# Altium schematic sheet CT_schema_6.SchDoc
size 257 x 245 mm
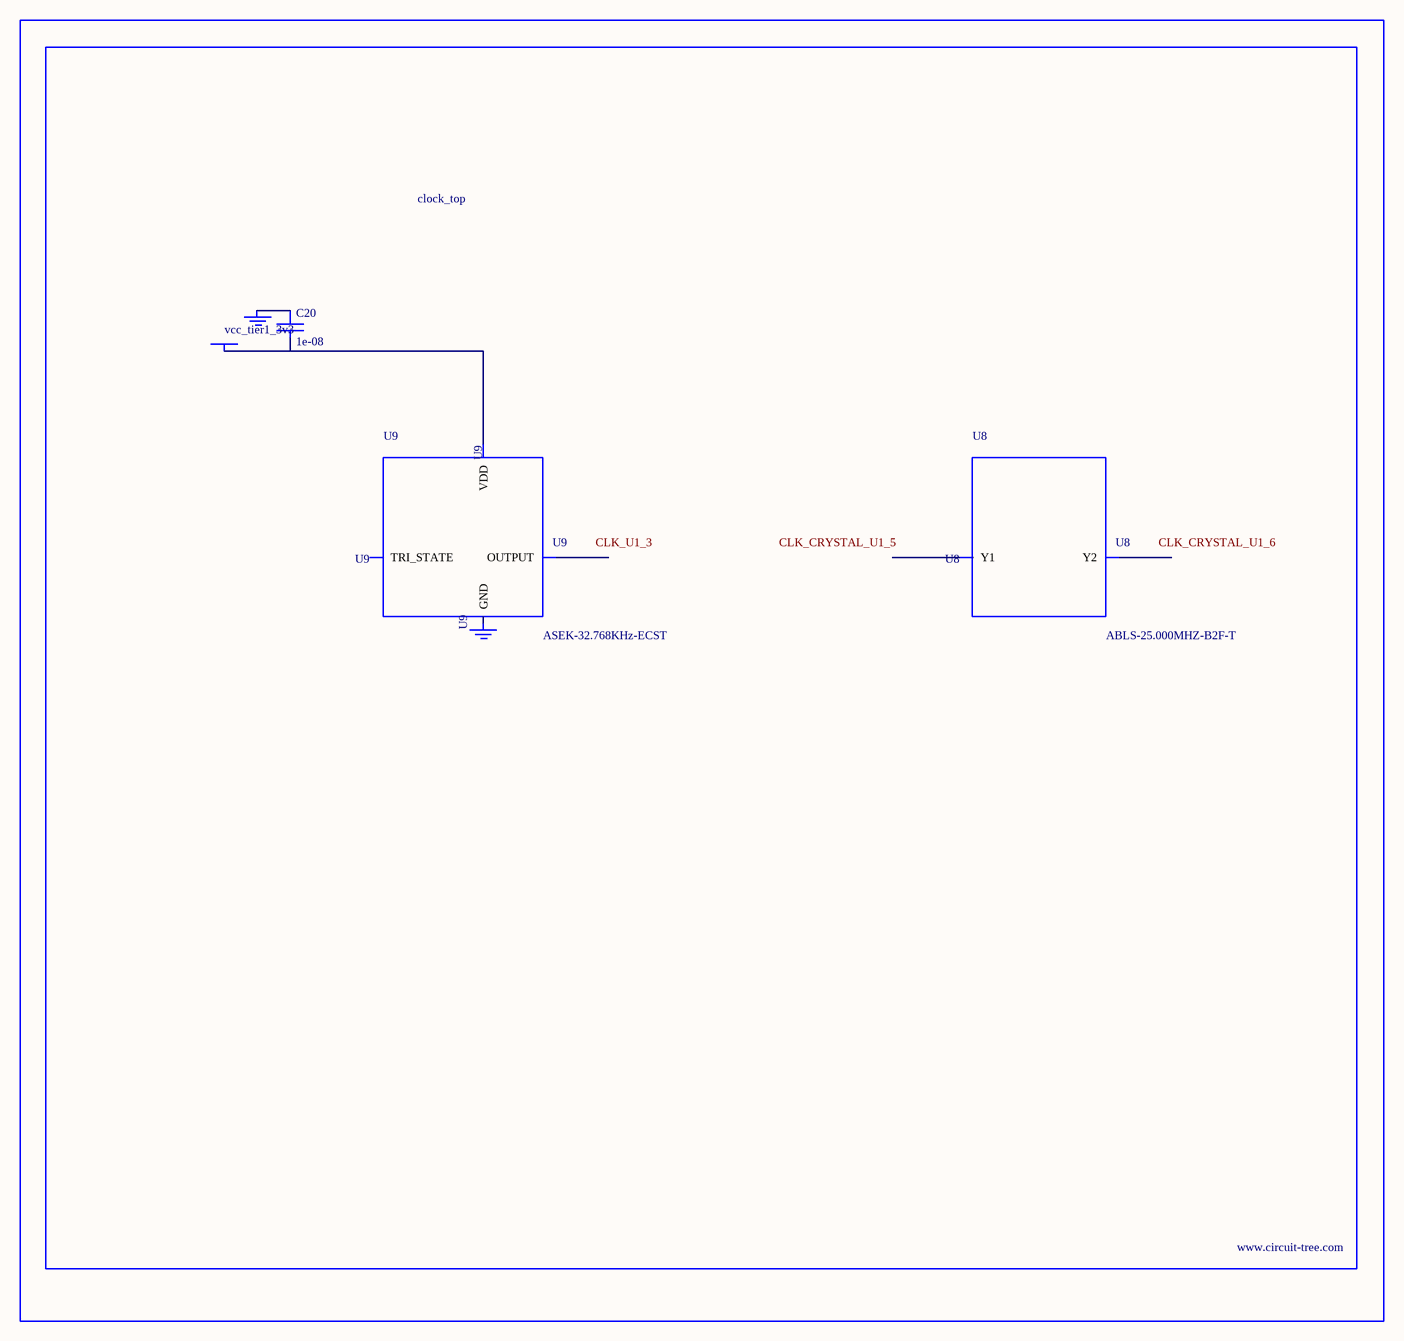
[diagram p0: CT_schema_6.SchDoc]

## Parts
BORDER5  (no value)
C20  1e-08  [C0402]
GND_INSTANCE_5_0  (no value)
GND_INSTANCE_5_1  (no value)
POWER_INSTANCE_5_0  vcc_tier1_3v3
U8  ABLS-25.000MHZ-B2F-T  [ABLS-25.000MHZ-B2F-T]
U9  ASEK-32.768KHz-ECST  [ASEK]

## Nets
NetC20_1: C20.1 GND_INSTANCE_5_0.0(GND)
NetC20_2: C20.2 POWER_INSTANCE_5_0.0(PWR) U9.4(VDD)

Not connected (* = marked no-connect by the designer): GND_INSTANCE_5_1 0(GND); U8 1(Y1) 2(Y2); U9 1(TRI_STATE) 2(GND) 3(OUTPUT)

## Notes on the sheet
- Labels drawn without touching a wire or pin: CLK_CRYSTAL_U1_5, CLK_CRYSTAL_U1_6, CLK_U1_3

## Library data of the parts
BORDER5 = BORDER_PAGE5
C20 = C0402C103K3RAC
GND_INSTANCE_5_0 GND_INSTANCE_5_1 = GND
POWER_INSTANCE_5_0 = PWR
